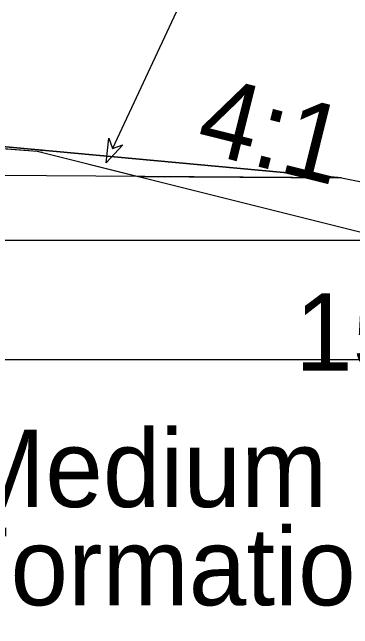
# Model space of a CAD drawing. Extents: x -516 to 303, y -10 to 5017.
# Drawn here: x 172.52 to 179.11, y 2994.79 to 3006.72 of the extents above; entities that cross this region are included whole.
import ezdxf

# ---------------------------------------------------------------- set-up
doc = ezdxf.new("R2010")
doc.units = 0
for name, color, linetype in [('Exist Cross Section Cell', 7, 'Continuous'), ('Exist XS Ground Line', 7, 'Continuous'), ('Prop CMT Slope Grass', 7, 'Continuous'), ('Prop Road Sect_ Material - Contact (General - Major)', 7, 'Continuous'), ('Prop Road Sect_ Material - Contact (General - Minor)', 7, 'Continuous'), ('Prop Road Sect_ Material - Tx (Composite Desc)', 7, 'Continuous'), ('Prop Road Sect_ Misc - Drafting Aid (Tx - small)', 7, 'Continuous'), ('Prop Road Sect_ Recs - UUC (Outline)', 7, 'Continuous'), ('Prop Road Sect_ Recs - UUC (pattern)', 7, 'Continuous'), ('Prop XS Ditch Standard Text', 7, 'Continuous'), ('Prop XS Side Slope Text', 7, 'Continuous'), ('Scratch_Level_0', 7, 'Continuous')]:
    doc.layers.add(name, color=color, linetype=linetype)

msp = doc.modelspace()

# ---------------------------------------------------------------- linework, layer by layer
at = {"layer": 'Exist Cross Section Cell'}
msp.add_line((150, 3000), (300, 3000), dxfattribs=at)
at = {"layer": 'Exist XS Ground Line'}
msp.add_lwpolyline([(165.597, 3004.599), (166.181, 3004.58), (166.527, 3004.557), (167.796, 3004.529), (168.1, 3004.519), (170.919, 3004.256), (178.897, 3003.518), (184.673, 3002.362), (189.348, 3001.486), (191.273, 3002.077), (195.067, 3003.07), (196.224, 3002.847), (199.834, 3002.922), (206.553, 3003.06)], dxfattribs=at)
at = {"layer": 'Prop CMT Slope Grass'}
for p, q in [((170, 3004.274), (173, 3004.034)), ((173, 3004.034), (181, 3002.034))]:
    msp.add_line(p, q, dxfattribs=at)
at = {"layer": 'Prop Road Sect_ Material - Contact (General - Major)'}
msp.add_line((178.897, 3003.518), (2.457, 3004.705), dxfattribs=at)
at = {"layer": 'Prop Road Sect_ Material - Contact (General - Minor)'}
msp.add_line((120.547, 3002.312), (184.938, 3002.312), dxfattribs=at)
at = {"layer": 'Prop Road Sect_ Misc - Drafting Aid (Tx - small)'}
msp.add_line((175.692, 3006.723), (174.462, 3004.085), dxfattribs=at)
msp.add_lwpolyline([(174.662, 3004.158), (174.335, 3003.812), (174.389, 3004.285), (174.462, 3004.085)], close=True, dxfattribs=at)
at = {"layer": 'Prop Road Sect_ Recs - UUC (Outline)'}
msp.add_lwpolyline([(166.527, 3004.557), (166.181, 3004.58), (166.168, 3004.581), (170, 3004.274), (173, 3004.034), (174.959, 3003.544), (178.897, 3003.518), (170.919, 3004.256), (168.1, 3004.519), (167.796, 3004.529)], close=True, dxfattribs=at)
at = {"layer": 'Prop Road Sect_ Recs - UUC (pattern)'}
msp.add_lwpolyline([(170, 3004.274), (173, 3004.034), (174.959, 3003.544), (178.897, 3003.518), (170.919, 3004.256), (168.1, 3004.519), (167.796, 3004.529), (166.527, 3004.557), (166.181, 3004.58)], dxfattribs=at)

# ---------------------------------------------------------------- texts
at = {"layer": 'Prop Road Sect_ Material - Tx (Composite Desc)'}
for s, p in [('COASTAL PLAIN: Orange-Brown and Gray, Soft to Medium ', (125.332, 2997.147)), ('Stiff, Sandy CLAY (A-6), Moist to Wet (Black Creek Formation)', (125.332, 2995.246))]:
    msp.add_text(s, height=1.5, dxfattribs=at).set_placement(p)
at = {"layer": 'Prop XS Ditch Standard Text'}
msp.add_text('159.03', height=1.5, dxfattribs=at).set_placement((177.995, 2999.784))
at = {"layer": 'Prop XS Side Slope Text'}
msp.add_text('4:1', height=1.5, rotation=345.9638, dxfattribs=at).set_placement((176.029, 3004.05))
at = {"layer": 'Scratch_Level_0'}
msp.add_text('RT_GS_OS_CTL', height=0.02, dxfattribs=at).set_placement((172.893, 3004.024))

doc.saveas('drawing.dxf')
